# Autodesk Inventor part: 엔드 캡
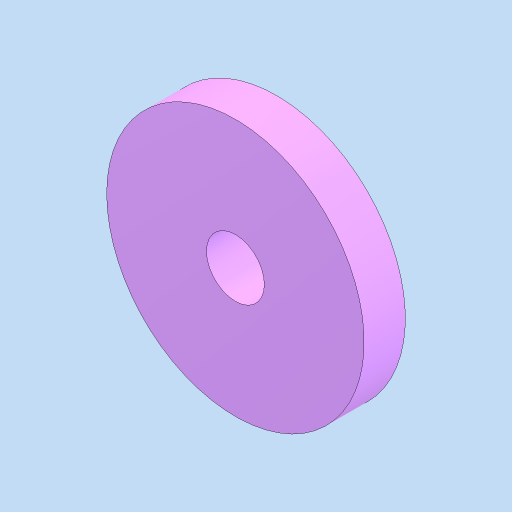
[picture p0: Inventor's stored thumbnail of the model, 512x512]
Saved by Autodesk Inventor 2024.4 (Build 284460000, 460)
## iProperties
Created: 2026-07
Part Number: 엔드 캡
Material: 강철, 연강
Document SubType Name: Modeling
Designer: home
Density: 7.85 g/cm^3
Appearance: 기본값
Author: jhkim
Sending System: Autodesk Inventor 2027
Preprocessor: ST-DEVELOPER v20.1
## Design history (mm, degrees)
feature "솔리드1"
node "솔리드2"
